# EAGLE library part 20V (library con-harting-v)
CONNECTOR
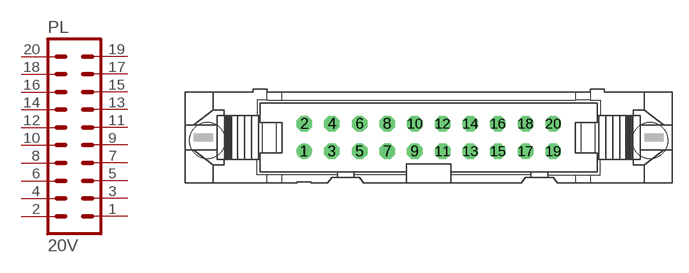
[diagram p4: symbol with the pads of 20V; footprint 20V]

Designator prefix PL

## 20V (OC_FARNELL: unknown; OC_NEWARK: unknown)  [20V]
1  1  pas
2  2  pas
3  3  pas
4  4  pas
5  5  pas
6  6  pas
7  7  pas
8  8  pas
9  9  pas
10  10  pas
11  11  pas
12  12  pas
13  13  pas
14  14  pas
15  15  pas
16  16  pas
17  17  pas
18  18  pas
19  19  pas
20  20  pas

## Footprint 20V (pad centres in mm)
CONNECTOR
drill 0.914 round: 1 -11.43,-1.27
drill 0.914 octagon: 2 -11.43,1.27; 3 -8.89,-1.27; 4 -8.89,1.27; 5 -6.35,-1.27; 6 -6.35,1.27; 7 -3.81,-1.27; 8 -3.81,1.27; 9 -1.27,-1.27; 10 -1.27,1.27; 11 1.27,-1.27; 12 1.27,1.27; 13 3.81,-1.27; 14 3.81,1.27; 15 6.35,-1.27; 16 6.35,1.27; 17 8.89,-1.27; 18 8.89,1.27; 19 11.43,-1.27; 20 11.43,1.27
hole 3.302 at 20.32,-0.254
hole 3.302 at -20.32,-0.254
